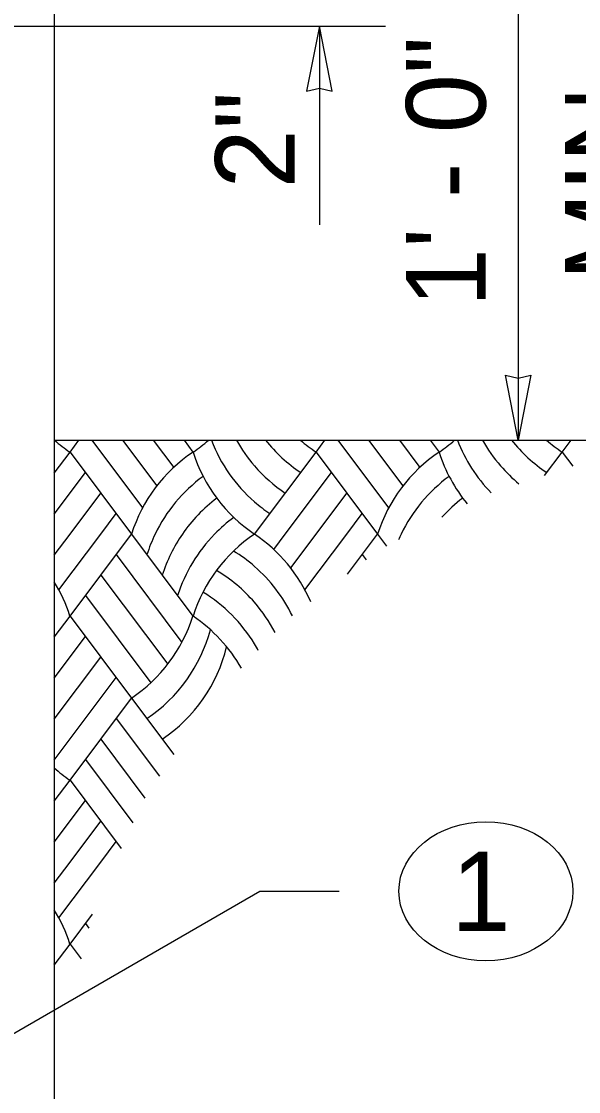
# Model space of a CAD drawing. Extents: x 99862 to 104211, y 98939 to 105076.
# Drawn here: x 101916.6 to 102028.6, y 101522 to 101737.3 of the extents above; entities that cross this region are included whole.
import ezdxf

# ---------------------------------------------------------------- set-up
doc = ezdxf.new("R2010")
doc.units = 0
for name, color, linetype in [('Level 15', 7, 'Continuous'), ('Level 2', 7, 'Continuous'), ('Level 20', 7, 'Continuous')]:
    doc.layers.add(name, color=color, linetype=linetype)

msp = doc.modelspace()

# ---------------------------------------------------------------- linework, layer by layer
at = {"layer": 'Level 15'}
for p, q in [((102016.49, 101753.04), (102016.49, 101653.04)), ((101904.71, 101736.37), (101989.82, 101736.37)), ((101976.49, 101736.37), (101976.49, 101696.37)), ((101923.16, 101653.04), (102064.35, 101653.04)), ((101926.33, 101650.65), (101928.12, 101653.04)), ((101930.72, 101653.04), (101940.93, 101639.42)), ((101936.9, 101653.04), (101943.8, 101643.85)), ((101943.09, 101653.04), (101947.2, 101647.57)), ((101949.28, 101653.04), (101951.07, 101650.65)), ((101975.82, 101650.65), (101977.62, 101653.04)), ((101980.21, 101653.04), (101990.43, 101639.42)), ((101986.4, 101653.04), (101993.3, 101643.85)), ((101992.59, 101653.04), (101996.69, 101647.57)), ((101998.78, 101653.04), (102000.57, 101650.65)), ((102025.32, 101650.65), (102027.12, 101653.04)), ((101923.16, 101646.42), (101926.33, 101650.65)), ((101926.33, 101650.65), (101938.7, 101634.15)), ((101963.45, 101634.15), (101975.82, 101650.65)), ((101975.82, 101650.65), (101988.2, 101634.15)), ((102021.81, 101645.96), (102025.32, 101650.65)), ((102025.32, 101650.65), (102027.45, 101647.8)), ((101923.16, 101638.17), (101929.42, 101646.52)), ((101969.64, 101634.15), (101978.92, 101646.52)), ((101926.33, 101634.15), (101932.51, 101642.4)), ((101975.82, 101634.15), (101982.01, 101642.4)), ((101932.51, 101634.15), (101935.61, 101638.27)), ((101982.01, 101634.15), (101985.1, 101638.27)), ((101923.16, 101629.92), (101926.33, 101634.15)), ((101924.1, 101622.93), (101932.51, 101634.15)), ((101926.33, 101617.65), (101938.7, 101634.15)), ((101938.7, 101634.15), (101951.07, 101617.65)), ((101967.33, 101631.07), (101969.64, 101634.15)), ((101970.72, 101627.35), (101975.82, 101634.15)), ((101973.59, 101622.93), (101982.01, 101634.15)), ((101982.17, 101626.11), (101988.2, 101634.15)), ((101988.2, 101634.15), (101990, 101631.74)), ((101935.61, 101630.02), (101948.85, 101612.37)), ((101985.1, 101630.02), (101985.91, 101628.95)), ((101932.51, 101625.9), (101945.98, 101607.95)), ((101929.42, 101621.77), (101942.58, 101604.23)), ((101923.16, 101613.42), (101926.33, 101617.65)), ((101926.33, 101617.65), (101938.7, 101601.15)), ((101923.16, 101605.17), (101929.42, 101613.52)), ((101923.16, 101596.92), (101932.51, 101609.4)), ((101923.16, 101588.67), (101935.61, 101605.27)), ((101926.33, 101584.65), (101938.7, 101601.15)), ((101938.7, 101601.15), (101947.22, 101589.79)), ((101935.61, 101597.02), (101944.31, 101585.42)), ((101932.51, 101592.9), (101941.4, 101581.04)), ((101929.42, 101588.77), (101938.94, 101576.08)), ((101923.16, 101580.42), (101926.33, 101584.65)), ((101926.33, 101584.65), (101936.63, 101570.91)), ((101923.16, 101572.17), (101929.42, 101580.52)), ((101926.33, 101568.15), (101932.51, 101576.4)), ((101932.51, 101568.15), (101935.61, 101572.27)), ((101923.16, 101563.92), (101926.33, 101568.15)), ((101924.1, 101556.93), (101932.51, 101568.15)), ((101903.16, 101526.87), (101964.49, 101562.28)), ((101964.49, 101562.28), (101980.49, 101562.28)), ((101926.33, 101551.65), (101930.86, 101557.7)), ((101929.42, 101555.78), (101930.13, 101554.83)), ((101923.16, 101547.42), (101926.33, 101551.65)), ((101926.33, 101551.65), (101928.55, 101548.69))]:
    msp.add_line(p, q, dxfattribs=at)
for points in [[(101976.49, 101736.37), (101973.92, 101723.27), (101976.49, 101723.88), (101979.06, 101723.27)], [(102016.49, 101653.04), (102013.92, 101666.14), (102016.49, 101665.54), (102019.06, 101666.14)]]:
    msp.add_lwpolyline(points, close=True, dxfattribs=at)
for centre, start, end in [((101943.79, 101676.64), 228.8961, 236.0964), ((101933.61, 101676.64), 303.9036, 311.1039), ((101984.01, 101664.26), 200.9992, 228.9599), ((101987.1, 101668.39), 209.3456, 220.9416), ((101990.2, 101672.51), 218.4475, 236.0964), ((101993.29, 101676.64), 228.8961, 236.0964), ((101983.1, 101676.64), 303.9036, 311.1039), ((102033.51, 101664.26), 200.9992, 224.13), ((102036.6, 101668.39), 209.3456, 220.9416), ((102039.69, 101672.51), 218.4475, 236.0964), ((102042.79, 101676.64), 228.8961, 236.0964), ((101968.54, 101624.66), 123.9036, 162.3566), ((101980.92, 101660.14), 197.6434, 236.0964), ((102018.04, 101624.66), 123.9036, 162.3566), ((102030.41, 101660.14), 197.6434, 219.4646), ((101940.7, 101672.51), 235.9296, 236.0964), ((101987.1, 101668.39), 220.9415, 236.0964), ((102036.6, 101668.39), 220.9415, 230.3515), ((101971.64, 101620.53), 126.3063, 154.2266), ((102021.13, 101620.53), 126.3063, 154.2266), ((101974.73, 101616.41), 127.1006, 145.4911), ((101984.01, 101664.26), 228.9599, 236.0964), ((102024.23, 101616.41), 127.1006, 137.4794), ((101977.82, 101612.28), 126.331, 135.7128), ((101971.64, 101620.53), 154.2265, 162.3566), ((101974.73, 101616.41), 145.491, 162.3566), ((101977.82, 101612.28), 135.7127, 162.3566), ((101980.92, 101608.16), 123.9036, 162.3566), ((101945.98, 101608.16), 23.1875, 56.0963), ((102021.13, 101620.53), 154.2265, 156.5373), ((101942.89, 101604.03), 48.9597, 58.5465), ((101942.89, 101604.03), 25.84, 48.9597), ((101939.79, 101599.91), 40.9413, 59.3021), ((101896.48, 101608.16), 17.6434, 31.5968), ((101936.7, 101595.78), 31.3316, 58.4874), ((101939.79, 101599.91), 27.4431, 40.9414), ((101921.23, 101627.14), 303.9036, 342.3566), ((101933.61, 101591.66), 29.6318, 56.0964), ((101924.33, 101623.01), 303.9036, 345.0113), ((101893.39, 101604.03), 17.6434, 18.0942), ((101936.7, 101595.78), 28.5404, 31.3317), ((101927.42, 101618.89), 303.9036, 346.3199), ((101943.79, 101610.64), 228.7762, 236.0964), ((101940.7, 101606.51), 235.9296, 236.0964), ((101896.48, 101542.16), 17.6434, 31.5968), ((101893.39, 101538.03), 17.6434, 18.0942)]:
    msp.add_arc(centre, 31.31, start, end, dxfattribs=at)
at = {"layer": 'Level 2'}
msp.add_line((101923.16, 101753.04), (101923.16, 101353.04), dxfattribs=at)
at = {"layer": 'Level 20'}
msp.add_ellipse((102009.99, 101562.28), major_axis=(17.5, 0), ratio=0.8, dxfattribs=at)

# ---------------------------------------------------------------- texts
for s, p in [('1\' - 0"', (102009.93, 101679.82)), ('MIN.', (102041.93, 101685.13)), ('2"', (101971.54, 101703.7))]:
    msp.add_text(s, height=16, rotation=90, dxfattribs=at).set_placement(p)
msp.add_text('1', height=16, dxfattribs=at).set_placement((102003.04, 101554.28))

doc.saveas('drawing.dxf')
